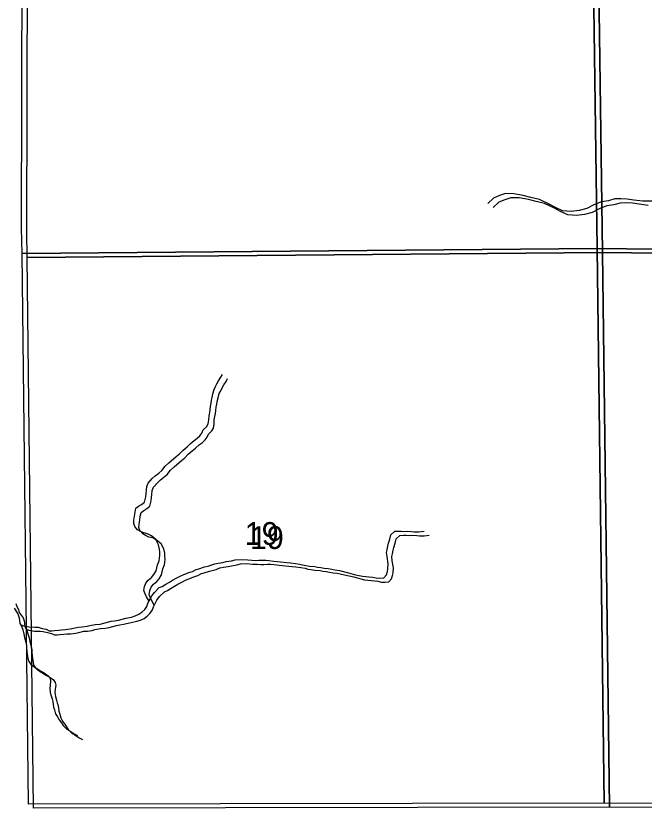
# Model space of a CAD drawing. Extents: x -21.1 to 50.3, y -4.9 to 22.1.
# Drawn here: x 44.094 to 45.249, y 15.653 to 17.109 of the extents above; entities that cross this region are included whole.
import ezdxf

# ---------------------------------------------------------------- set-up
doc = ezdxf.new("R2010")
doc.units = 0
for name, color, linetype in [('GM_X_Minor_River', 7, 'Continuous'), ('GM_X_Section', 7, 'Continuous'), ('GM_X_Section_Text', 7, 'Continuous')]:
    doc.layers.add(name, color=color, linetype=linetype)

msp = doc.modelspace()

# ---------------------------------------------------------------- linework, layer by layer
at = {"layer": 'GM_X_Minor_River'}
for points in [[(45.1567, 16.7617), (45.1438, 16.7551), (45.1298, 16.7513), (45.1153, 16.7497), (45.0989, 16.7507), (45.086, 16.7567), (45.0745, 16.7631), (45.0566, 16.7714), (45.0409, 16.7751), (45.0268, 16.7792), (45.0097, 16.7821), (44.9945, 16.7824), (44.9834, 16.7786), (44.9721, 16.7739), (44.9618, 16.7644)], [(45.1664, 16.7542), (45.1535, 16.7476), (45.1394, 16.7438), (45.1249, 16.7422), (45.1086, 16.7432), (45.0956, 16.7492), (45.0841, 16.7556), (45.0662, 16.7639), (45.0506, 16.7676), (45.0365, 16.7717), (45.0193, 16.7746), (45.0041, 16.7749), (44.9931, 16.7711), (44.9817, 16.7664), (44.9715, 16.7569)], [(45.2663, 16.7684), (45.2469, 16.7682), (45.2302, 16.7704), (45.2183, 16.7723), (45.2062, 16.773), (45.1955, 16.7725), (45.1837, 16.7694), (45.1708, 16.7674), (45.1567, 16.7617)], [(45.2565, 16.7607), (45.2398, 16.7629), (45.228, 16.7648), (45.2158, 16.7655), (45.2051, 16.765), (45.1934, 16.7619), (45.1804, 16.7599), (45.1664, 16.7542)], [(44.3388, 16.0336), (44.3341, 16.0415), (44.3318, 16.0472), (44.3291, 16.0529), (44.3305, 16.0605), (44.3328, 16.0666), (44.3373, 16.0723), (44.3433, 16.0769), (44.3478, 16.0823), (44.352, 16.0892), (44.3531, 16.0949), (44.3545, 16.1002), (44.3575, 16.1078), (44.3589, 16.1174), (44.3585, 16.1238), (44.3581, 16.1291), (44.3561, 16.1371), (44.3515, 16.1466), (44.3431, 16.1534), (44.3362, 16.1571), (44.3289, 16.1589), (44.324, 16.1612), (44.3175, 16.1645), (44.3125, 16.171), (44.3105, 16.1763), (44.3109, 16.1824), (44.3119, 16.19), (44.313, 16.1972), (44.3145, 16.2041), (44.3194, 16.2079), (44.3251, 16.211), (44.3304, 16.2156), (44.3329, 16.2255), (44.3336, 16.2312), (44.334, 16.2373), (44.3347, 16.2445), (44.3373, 16.2506), (44.3444, 16.2587), (44.3501, 16.2637), (44.3565, 16.2687), (44.3622, 16.2737), (44.3686, 16.2817), (44.3754, 16.2878), (44.3886, 16.2994), (44.395, 16.3044), (44.4014, 16.3109), (44.4086, 16.3174), (44.4146, 16.3224), (44.4218, 16.3289), (44.4275, 16.3328), (44.4324, 16.3374), (44.4361, 16.3423), (44.4384, 16.3481), (44.4444, 16.3538), (44.4474, 16.3592), (44.4488, 16.3668), (44.4492, 16.374), (44.4503, 16.3801), (44.4513, 16.3858), (44.4517, 16.3915), (44.4528, 16.3976), (44.4539, 16.4029), (44.4546, 16.4079), (44.456, 16.4147), (44.4583, 16.4224), (44.4609, 16.4277), (44.4635, 16.4327), (44.4665, 16.4384), (44.4706, 16.4449), (44.4736, 16.4503)], [(44.3484, 16.0261), (44.3437, 16.034), (44.3414, 16.0397), (44.3387, 16.0453), (44.3402, 16.053), (44.3424, 16.0591), (44.3469, 16.0648), (44.353, 16.0694), (44.3575, 16.0748), (44.3616, 16.0817), (44.3627, 16.0874), (44.3642, 16.0927), (44.3671, 16.1003), (44.3686, 16.1099), (44.3681, 16.1163), (44.3677, 16.1216), (44.3658, 16.1296), (44.3611, 16.1391), (44.3527, 16.1458), (44.3458, 16.1496), (44.3386, 16.1514), (44.3336, 16.1537), (44.3271, 16.157), (44.3221, 16.1635), (44.3202, 16.1688), (44.3205, 16.1749), (44.3216, 16.1825), (44.3227, 16.1897), (44.3241, 16.1966), (44.329, 16.2004), (44.3347, 16.2035), (44.34, 16.2081), (44.3426, 16.218), (44.3433, 16.2237), (44.3436, 16.2298), (44.3443, 16.237), (44.3469, 16.2431), (44.3541, 16.2512), (44.3597, 16.2562), (44.3662, 16.2612), (44.3718, 16.2662), (44.3782, 16.2742), (44.385, 16.2803), (44.3982, 16.2919), (44.4046, 16.2969), (44.411, 16.3034), (44.4182, 16.3099), (44.4243, 16.3149), (44.4314, 16.3214), (44.4371, 16.3253), (44.442, 16.3299), (44.4458, 16.3348), (44.448, 16.3406), (44.454, 16.3463), (44.457, 16.3517), (44.4585, 16.3593), (44.4588, 16.3665), (44.4599, 16.3726), (44.461, 16.3783), (44.4613, 16.384), (44.4624, 16.3901), (44.4635, 16.3954), (44.4642, 16.4004), (44.4657, 16.4072), (44.4679, 16.4149), (44.4705, 16.4202), (44.4731, 16.4252), (44.4761, 16.4309), (44.4803, 16.4374), (44.4833, 16.4428)], [(44.7793, 16.1398), (44.7815, 16.1474), (44.7837, 16.1554), (44.7905, 16.1619), (44.7973, 16.1624), (44.8023, 16.162), (44.8076, 16.1617), (44.8145, 16.1621), (44.8217, 16.1618), (44.8266, 16.1611), (44.835, 16.1612), (44.8445, 16.162)], [(44.7889, 16.1323), (44.7911, 16.1399), (44.7933, 16.1479), (44.8001, 16.1544), (44.807, 16.1549), (44.8119, 16.1545), (44.8173, 16.1542), (44.8241, 16.1546), (44.8313, 16.1543), (44.8363, 16.1536), (44.8446, 16.1537), (44.8541, 16.1545)], [(44.1027, 15.9902), (44.108, 15.9879), (44.1182, 15.9861), (44.1289, 15.9858), (44.1346, 15.9855), (44.1422, 15.9833), (44.1494, 15.9818), (44.1552, 15.9792), (44.1601, 15.9792), (44.1651, 15.9796), (44.1723, 15.9805), (44.178, 15.9809), (44.1852, 15.9813), (44.1939, 15.9825), (44.2, 15.9837), (44.2091, 15.9857), (44.216, 15.9861), (44.2247, 15.9874), (44.2296, 15.9889), (44.2399, 15.9905), (44.2486, 15.9914), (44.2558, 15.9929), (44.2691, 15.9965), (44.2752, 15.9973), (44.2824, 15.9989), (44.296, 16.002), (44.3067, 16.0044), (44.3135, 16.0063), (44.3199, 16.0094), (44.3256, 16.0133), (44.3309, 16.0183), (44.335, 16.024), (44.3372, 16.0309), (44.3406, 16.037), (44.3436, 16.0431), (44.3485, 16.0496), (44.3575, 16.0584), (44.3628, 16.0607), (44.3697, 16.065), (44.3761, 16.0684), (44.3818, 16.0723), (44.3897, 16.0762), (44.3973, 16.08), (44.4026, 16.0823), (44.4136, 16.0866), (44.4189, 16.0882), (44.4253, 16.0917), (44.4306, 16.0928), (44.4405, 16.0963), (44.4477, 16.0979), (44.4526, 16.0995), (44.4595, 16.1022), (44.4659, 16.1034), (44.4746, 16.1046), (44.4807, 16.1062), (44.4906, 16.1078), (44.4974, 16.1094), (44.5084, 16.1102), (44.5202, 16.1092), (44.5278, 16.1088), (44.5347, 16.1085), (44.5404, 16.1086), (44.5461, 16.109), (44.5533, 16.1087), (44.559, 16.1083), (44.5685, 16.1069), (44.5742, 16.1066), (44.5803, 16.1059), (44.5921, 16.1048), (44.599, 16.1041), (44.6081, 16.1027), (44.6161, 16.1016), (44.6211, 16.1001), (44.6268, 16.099), (44.634, 16.0979), (44.6435, 16.0972), (44.6485, 16.0961), (44.6549, 16.0954), (44.661, 16.0943), (44.6679, 16.0933), (44.6751, 16.0922), (44.6805, 16.0911), (44.6888, 16.0896), (44.7056, 16.0856), (44.7186, 16.0819), (44.7254, 16.0804), (44.7311, 16.0793), (44.7376, 16.079), (44.7498, 16.0776), (44.7566, 16.0761), (44.7631, 16.0758), (44.7703, 16.0766), (44.7752, 16.082), (44.7771, 16.0881), (44.7778, 16.093), (44.7785, 16.1021), (44.7764, 16.1154), (44.7756, 16.123), (44.7767, 16.128), (44.7778, 16.1345), (44.7793, 16.1398)], [(44.1123, 15.9827), (44.1176, 15.9804), (44.1279, 15.9786), (44.1385, 15.9783), (44.1442, 15.978), (44.1518, 15.9758), (44.1591, 15.9743), (44.1648, 15.9717), (44.1698, 15.9717), (44.1747, 15.9721), (44.1819, 15.973), (44.1876, 15.9734), (44.1948, 15.9738), (44.2036, 15.975), (44.2096, 15.9762), (44.2187, 15.9782), (44.2256, 15.9786), (44.2343, 15.9799), (44.2393, 15.9814), (44.2495, 15.983), (44.2582, 15.9839), (44.2655, 15.9854), (44.2787, 15.989), (44.2848, 15.9898), (44.292, 15.9914), (44.3057, 15.9945), (44.3163, 15.9969), (44.3231, 15.9988), (44.3296, 16.0019), (44.3352, 16.0058), (44.3405, 16.0108), (44.3447, 16.0165), (44.3469, 16.0234), (44.3503, 16.0295), (44.3532, 16.0356), (44.3581, 16.0421), (44.3672, 16.0509), (44.3725, 16.0532), (44.3793, 16.0575), (44.3857, 16.0609), (44.3914, 16.0648), (44.3993, 16.0687), (44.4069, 16.0725), (44.4122, 16.0748), (44.4232, 16.0791), (44.4285, 16.0807), (44.435, 16.0842), (44.4403, 16.0853), (44.4501, 16.0888), (44.4573, 16.0904), (44.4623, 16.092), (44.4691, 16.0947), (44.4755, 16.0959), (44.4843, 16.0971), (44.4903, 16.0987), (44.5002, 16.1003), (44.5071, 16.1019), (44.5181, 16.1027), (44.5299, 16.1017), (44.5375, 16.1013), (44.5443, 16.101), (44.55, 16.1011), (44.5557, 16.1015), (44.5629, 16.1012), (44.5687, 16.1008), (44.5782, 16.0994), (44.5839, 16.0991), (44.59, 16.0983), (44.6018, 16.0973), (44.6086, 16.0966), (44.6178, 16.0952), (44.6257, 16.0941), (44.6307, 16.0926), (44.6364, 16.0915), (44.6436, 16.0904), (44.6532, 16.0897), (44.6581, 16.0886), (44.6646, 16.0879), (44.6707, 16.0868), (44.6775, 16.0858), (44.6848, 16.0847), (44.6901, 16.0836), (44.6985, 16.0821), (44.7152, 16.0781), (44.7282, 16.0744), (44.735, 16.0729), (44.7408, 16.0718), (44.7472, 16.0715), (44.7594, 16.0701), (44.7663, 16.0686), (44.7727, 16.0683), (44.7799, 16.0691), (44.7848, 16.0745), (44.7867, 16.0806), (44.7874, 16.0855), (44.7881, 16.0946), (44.7861, 16.1079), (44.7853, 16.1155), (44.7864, 16.1205), (44.7874, 16.127), (44.7889, 16.1323)], [(44.0936, 16.0293), (44.0959, 16.0236), (44.0986, 16.0183), (44.1002, 16.013), (44.1071, 16.0028), (44.1095, 15.9956), (44.1099, 15.9899), (44.1111, 15.9849), (44.1138, 15.98), (44.1161, 15.9736), (44.1181, 15.966), (44.1197, 15.9595), (44.122, 15.9504), (44.1232, 15.9443), (44.1233, 15.9394), (44.1237, 15.9345), (44.1245, 15.928), (44.1257, 15.9212), (44.1265, 15.9162), (44.1303, 15.9106), (44.1369, 15.9053), (44.1418, 15.9023), (44.1491, 15.8978), (44.1552, 15.8944), (44.1628, 15.8888), (44.1663, 15.8839), (44.1671, 15.8789), (44.1664, 15.8717), (44.1657, 15.866), (44.1665, 15.8584), (44.1685, 15.8519), (44.1701, 15.8466), (44.1716, 15.8417), (44.1728, 15.8314), (44.1744, 15.8261), (44.1764, 15.8189), (44.1798, 15.8132), (44.1833, 15.8079), (44.1872, 15.8027), (44.1902, 15.7977), (44.1971, 15.7906), (44.2025, 15.7879), (44.2105, 15.7823), (44.2166, 15.7793)], [(44.0906, 16.0205), (44.0975, 16.0103), (44.0998, 16.0031), (44.1003, 15.9974), (44.1014, 15.9924), (44.1042, 15.9875), (44.1065, 15.9811), (44.1085, 15.9735), (44.11, 15.967), (44.1124, 15.9579), (44.1136, 15.9518), (44.1136, 15.9469), (44.114, 15.942), (44.1149, 15.9355), (44.1161, 15.9287), (44.1169, 15.9237), (44.1207, 15.9181), (44.1272, 15.9128), (44.1322, 15.9098), (44.1394, 15.9053), (44.1456, 15.9019), (44.1532, 15.8963), (44.1567, 15.8914), (44.1575, 15.8864), (44.1568, 15.8792), (44.1561, 15.8735), (44.1569, 15.8659), (44.1588, 15.8594), (44.1604, 15.8541), (44.162, 15.8492), (44.1632, 15.8389), (44.1648, 15.8336), (44.1667, 15.8264), (44.1702, 15.8207), (44.1737, 15.8154), (44.1775, 15.8102), (44.1806, 15.8052), (44.1875, 15.7981), (44.1928, 15.7954), (44.2009, 15.7898), (44.207, 15.7868)]]:
    msp.add_lwpolyline(points, dxfattribs=at)
at = {"layer": 'GM_X_Section'}
for points in [[(45.1486, 17.7019), (45.1628, 16.6817), (44.1053, 16.6722), (44.1042, 16.7188), (44.1067, 17.6888)], [(45.1583, 17.6944), (45.1724, 16.6742), (44.1149, 16.6647), (44.1138, 16.7113), (44.1163, 17.6813)], [(46.1737, 17.6801), (46.1885, 16.6701), (45.1628, 16.6817), (45.1486, 17.7019), (45.7604, 17.6964)], [(46.1834, 17.6726), (46.1982, 16.6626), (45.1724, 16.6742), (45.1583, 17.6944), (45.7701, 17.6889)], [(45.1628, 16.6817), (45.1757, 15.6626), (44.1168, 15.6607), (44.1053, 16.6722)], [(45.1724, 16.6742), (45.1854, 15.6551), (44.1264, 15.6532), (44.1149, 16.6647)], [(45.1628, 16.6817), (46.1885, 16.6701), (46.2007, 15.6608), (45.1757, 15.6626)], [(45.1724, 16.6742), (46.1982, 16.6626), (46.2103, 15.6533), (45.1854, 15.6551)]]:
    msp.add_lwpolyline(points, close=True, dxfattribs=at)

# ---------------------------------------------------------------- texts
at = {"layer": 'GM_X_Section_Text'}
for p in [(44.5147, 16.1369), (44.5243, 16.1294)]:
    msp.add_text('19', height=0.04186, rotation=0, dxfattribs=at).set_placement(p)

doc.saveas('drawing.dxf')
